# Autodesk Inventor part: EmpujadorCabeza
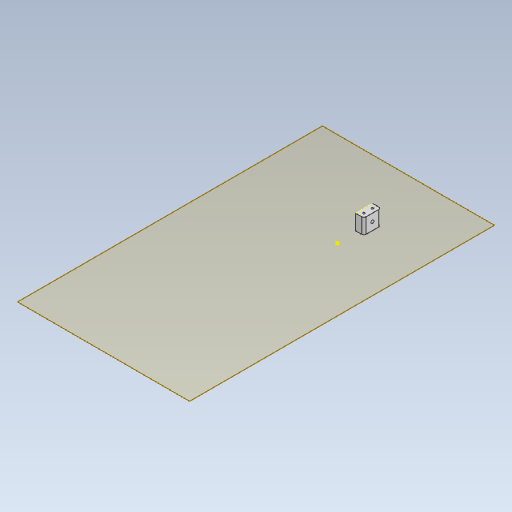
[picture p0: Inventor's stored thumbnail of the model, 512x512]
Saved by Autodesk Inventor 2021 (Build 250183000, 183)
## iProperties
Created: 2021-02
Part Number: EmpujadorCabeza
Material: Genérico
Document SubType Name: Modeling
Designer: ATOUZA
Mass: 27.4687 g
Surface Area: 54.711 cm^2
Volume: 27.4687 cm^3
Density: 1 g/cm^3
Appearance: Valor por defecto
Author: ATOUZA
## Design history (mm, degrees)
node "Plano de trabajo1"
sketch "Boceto1"
  geometry: L1 (0, -16)-(16, -16); L2 (16, -16)-(16, 16); L3 (16, 16)-(0, 16); L4 (0, 16)-(0, -16); L5 (0, -16)-(16, 16); L6 (16, -16)-(0, 16); L7 (0, 16)-(0, 0); L8 (0, 8)-(16, 8); L9 (0, 0)-(0, -16); L10 (0, -8)-(16, -8); C1 r 1.9 at (8, 8); C2 r 1.9 at (8, -8); 2 further points
  constraints: 20 end point, 7 midpoint, 2 centre point, 2 horizontal, 2 parallel, 2 perpendicular, 1 vertical
  dimensions: "d23" = 16 distance of L3.end L2.end; "d24" = 32 distance of L2.end L1.end; "d35" = 3.8 diameter of C1; "d36" = 3.8 diameter of C2
extrude "Extrusión2" new body sketch "Boceto1" distance "d29" = 28.5; taper "d30" = 0 deg
fillet "Empalme4" dims "d37" = 4
sketch "Boceto5"
  geometry: L1 (0, 0)-(0, 28.5) reference; L2 (0, 14.5)-(31.407, 14.5); L3 (0, 28.5)-(32, 28.5) reference; C1 r 2.9 at (16, 14.5); 1 further point
  constraints: 2 end point, 2 point on line, 1 centre point, 1 horizontal
  dimensions: "d38" = 5.8 diameter of C1; "d41" = 14 distance from line of L3 C1.centre
extrude "Extrusión4" cut sketch "Boceto5" extent not by distance; stored distance "d39" = 0; taper "d40" = 0 deg
node "Sólido2"
other parameters: "d3" = 16
